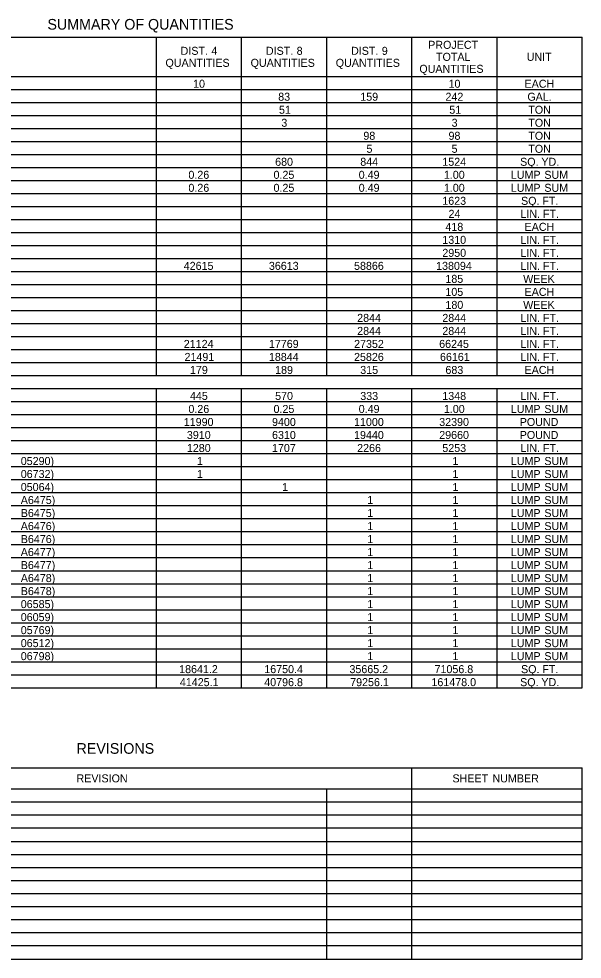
# Model space of a CAD drawing. Extents: x 544420 to 1930787, y -1947044 to 596640.
# Drawn here: x 552521 to 552943, y -1946914 to -1946209 of the extents above; entities that cross this region are included whole.
import ezdxf

# ---------------------------------------------------------------- set-up
doc = ezdxf.new("R2010")
doc.units = 0
doc.layers.add('Default', color=7, linetype='Continuous')

msp = doc.modelspace()

# ---------------------------------------------------------------- linework, layer by layer
at = {"layer": 'Default'}
for p, q in [((552192.61, -1946223.24), (552943.36, -1946223.24)), ((552624.05, -1946476.74), (552624.05, -1946223.24)), ((552624.05, -1946476.74), (552624.05, -1946223.24)), ((552687.91, -1946476.74), (552687.91, -1946223.24)), ((552687.91, -1946252.49), (552687.91, -1946223.24)), ((552751.77, -1946476.74), (552751.77, -1946223.24)), ((552751.77, -1946252.49), (552751.77, -1946223.24)), ((552815.63, -1946476.74), (552815.63, -1946223.24)), ((552879.5, -1946476.74), (552879.5, -1946223.24)), ((552879.5, -1946476.74), (552879.5, -1946223.24)), ((552943.36, -1946710.74), (552943.36, -1946223.24)), ((552192.61, -1946252.49), (552943.36, -1946252.49)), ((552192.61, -1946252.49), (552943.36, -1946252.49)), ((552192.61, -1946262.24), (552943.36, -1946262.24)), ((552192.61, -1946271.99), (552943.36, -1946271.99)), ((552192.61, -1946281.74), (552943.36, -1946281.74)), ((552192.61, -1946291.49), (552943.36, -1946291.49)), ((552192.61, -1946301.24), (552943.36, -1946301.24)), ((552192.61, -1946310.99), (552943.36, -1946310.99)), ((552192.61, -1946320.74), (552943.36, -1946320.74)), ((552192.61, -1946330.49), (552943.36, -1946330.49)), ((552192.61, -1946340.24), (552943.36, -1946340.24)), ((552192.61, -1946349.99), (552943.36, -1946349.99)), ((552192.61, -1946359.74), (552943.36, -1946359.74)), ((552192.61, -1946369.49), (552943.36, -1946369.49)), ((552192.61, -1946379.24), (552943.36, -1946379.24)), ((552192.61, -1946388.99), (552943.36, -1946388.99)), ((552192.61, -1946398.74), (552943.36, -1946398.74)), ((552192.61, -1946408.49), (552943.36, -1946408.49)), ((552192.61, -1946418.24), (552943.36, -1946418.24)), ((552192.61, -1946427.99), (552943.36, -1946427.99)), ((552192.61, -1946437.74), (552943.36, -1946437.74)), ((552192.61, -1946447.49), (552943.36, -1946447.49)), ((552192.61, -1946457.24), (552943.36, -1946457.24)), ((552192.61, -1946466.99), (552943.36, -1946466.99)), ((552192.61, -1946476.74), (552943.36, -1946476.74)), ((552192.61, -1946476.74), (552943.36, -1946476.74)), ((552192.61, -1946486.49), (552943.36, -1946486.49)), ((552192.61, -1946486.49), (552943.36, -1946486.49)), ((552624.05, -1946496.24), (552624.05, -1946486.49)), ((552624.05, -1946710.74), (552624.05, -1946486.49)), ((552687.91, -1946710.74), (552687.91, -1946486.49)), ((552751.77, -1946710.74), (552751.77, -1946486.49)), ((552815.63, -1946710.74), (552815.63, -1946486.49)), ((552879.5, -1946710.74), (552879.5, -1946486.49)), ((552879.5, -1946710.74), (552879.5, -1946486.49)), ((552192.61, -1946496.24), (552943.36, -1946496.24)), ((552192.61, -1946505.99), (552943.36, -1946505.99)), ((552624.05, -1946700.99), (552624.05, -1946505.99)), ((552192.61, -1946515.74), (552943.36, -1946515.74)), ((552563.11, -1946515.74), (552943.36, -1946515.74)), ((552192.61, -1946525.49), (552943.36, -1946525.49)), ((552563.11, -1946525.49), (552943.36, -1946525.49)), ((552192.61, -1946535.24), (552943.36, -1946535.24)), ((552563.11, -1946535.24), (552943.36, -1946535.24)), ((552192.61, -1946544.99), (552943.36, -1946544.99)), ((552263.3, -1946544.99), (552943.36, -1946544.99)), ((552192.61, -1946554.74), (552943.36, -1946554.74)), ((552263.3, -1946554.74), (552943.36, -1946554.74)), ((552192.61, -1946564.49), (552943.36, -1946564.49)), ((552263.3, -1946564.49), (552943.36, -1946564.49)), ((552192.61, -1946574.24), (552943.36, -1946574.24)), ((552263.3, -1946574.24), (552943.36, -1946574.24)), ((552192.61, -1946583.99), (552943.36, -1946583.99)), ((552263.3, -1946583.99), (552943.36, -1946583.99)), ((552192.61, -1946593.74), (552943.36, -1946593.74)), ((552263.3, -1946593.74), (552943.36, -1946593.74)), ((552192.61, -1946603.49), (552943.36, -1946603.49)), ((552263.3, -1946603.49), (552943.36, -1946603.49)), ((552192.61, -1946613.24), (552943.36, -1946613.24)), ((552263.3, -1946613.24), (552943.36, -1946613.24)), ((552192.61, -1946622.99), (552943.36, -1946622.99)), ((552263.3, -1946622.99), (552943.36, -1946622.99)), ((552192.61, -1946632.74), (552943.36, -1946632.74)), ((552263.3, -1946632.74), (552943.36, -1946632.74)), ((552192.61, -1946642.49), (552943.36, -1946642.49)), ((552263.3, -1946642.49), (552943.36, -1946642.49)), ((552192.61, -1946652.24), (552943.36, -1946652.24)), ((552263.3, -1946652.24), (552943.36, -1946652.24)), ((552192.61, -1946661.99), (552943.36, -1946661.99)), ((552263.3, -1946661.99), (552943.36, -1946661.99)), ((552192.61, -1946671.74), (552943.36, -1946671.74)), ((552263.3, -1946671.74), (552943.36, -1946671.74)), ((552192.61, -1946681.49), (552943.36, -1946681.49)), ((552263.3, -1946681.49), (552943.36, -1946681.49)), ((552192.61, -1946691.24), (552943.36, -1946691.24)), ((552263.3, -1946691.24), (552943.36, -1946691.24)), ((552192.61, -1946700.99), (552943.36, -1946700.99)), ((552563.11, -1946700.99), (552943.36, -1946700.99)), ((552192.61, -1946710.74), (552943.36, -1946710.74)), ((552192.61, -1946770.86), (552943.36, -1946770.86)), ((552815.63, -1946786.46), (552815.63, -1946770.86)), ((552815.63, -1946914.18), (552815.63, -1946770.86)), ((552943.36, -1946914.18), (552943.36, -1946770.86)), ((552192.61, -1946786.46), (552943.36, -1946786.46)), ((552751.77, -1946914.18), (552751.77, -1946786.46)), ((552751.77, -1946914.18), (552751.77, -1946786.46)), ((552192.61, -1946796.21), (552943.36, -1946796.21)), ((552192.61, -1946805.96), (552943.36, -1946805.96)), ((552192.61, -1946815.71), (552943.36, -1946815.71)), ((552192.61, -1946825.95), (552943.36, -1946825.95)), ((552192.61, -1946835.7), (552943.36, -1946835.7)), ((552192.61, -1946845.45), (552943.36, -1946845.45)), ((552192.61, -1946855.2), (552943.36, -1946855.2)), ((552192.61, -1946864.95), (552943.36, -1946864.95)), ((552192.61, -1946874.7), (552943.36, -1946874.7)), ((552192.61, -1946884.45), (552943.36, -1946884.45)), ((552192.61, -1946894.2), (552943.36, -1946894.2)), ((552192.61, -1946903.95), (552943.36, -1946903.95)), ((552192.61, -1946914.18), (552943.36, -1946914.18))]:
    msp.add_line(p, q, dxfattribs=at)

# ---------------------------------------------------------------- texts
for s, height, p in [('                                                                    SUMMARY OF QUANTITIES', 8, (552340.14, -1946217.49)), ('PROJECT', 6, (552827.85, -1946231.87)), ('DIST.', 6, (552642.15, -1946236.37)), (' 4', 6, (552663, -1946236.37)), ('DIST.', 6, (552706.11, -1946236.37)), (' 8', 6, (552726.96, -1946236.37)), ('DIST.', 6, (552769.98, -1946236.37)), (' 9', 6, (552790.83, -1946236.37)), ('TOTAL', 6, (552833.72, -1946240.87)), ('UNIT', 6, (552901.73, -1946240.87)), ('QUANTITIES', 6, (552630.8, -1946245.37)), ('QUANTITIES', 6, (552694.66, -1946245.37)), ('QUANTITIES', 6, (552758.52, -1946245.37)), ('QUANTITIES', 6, (552821.22, -1946249.87)), ('10', 6, (552651.52, -1946261.04)), ('10', 6, (552843.11, -1946261.04)), ('EACH', 6, (552900.12, -1946261.04)), ('83', 6, (552715.37, -1946270.79)), ('159', 6, (552776.9, -1946270.79)), ('242', 6, (552840.8, -1946270.79)), ('GAL.', 6, (552902.24, -1946270.79)), ('51', 6, (552715.95, -1946280.54)), ('51', 6, (552843.68, -1946280.54)), ('TON', 6, (552902.92, -1946280.54)), ('3', 6, (552717.7, -1946290.29)), ('3', 6, (552845.42, -1946290.29)), ('TON', 6, (552902.92, -1946290.29)), ('98', 6, (552779.23, -1946300.04)), ('98', 6, (552843.09, -1946300.04)), ('TON', 6, (552902.92, -1946300.04)), ('5', 6, (552781.54, -1946309.79)), ('5', 6, (552845.4, -1946309.79)), ('TON', 6, (552902.92, -1946309.79)), ('680', 6, (552713.05, -1946319.54)), ('844', 6, (552776.92, -1946319.54)), ('1524', 6, (552838.45, -1946319.54)), ('SQ.', 6, (552896.79, -1946319.54)), (' YD.', 6, (552910.5, -1946319.54)), ('0.26', 6, (552648.01, -1946329.29)), ('0.25', 6, (552711.85, -1946329.29)), ('0.49', 6, (552775.73, -1946329.29)), ('1.00', 6, (552839.61, -1946329.29)), ('LUMP', 6, (552889.8, -1946329.29)), (' SUM', 6, (552912.73, -1946329.29)), ('0.26', 6, (552648.01, -1946339.04)), ('0.25', 6, (552711.85, -1946339.04)), ('0.49', 6, (552775.73, -1946339.04)), ('1.00', 6, (552839.61, -1946339.04)), ('LUMP', 6, (552889.8, -1946339.04)), (' SUM', 6, (552912.73, -1946339.04)), ('1623', 6, (552838.43, -1946348.79)), ('SQ.', 6, (552897.49, -1946348.79)), (' FT.', 6, (552911.2, -1946348.79)), ('24', 6, (552843.11, -1946358.54)), ('LIN.', 6, (552897.02, -1946358.54)), (' FT.', 6, (552911.66, -1946358.54)), ('418', 6, (552840.76, -1946368.29)), ('EACH', 6, (552900.12, -1946368.29)), ('1310', 6, (552838.45, -1946378.04)), ('LIN.', 6, (552897.02, -1946378.04)), (' FT.', 6, (552911.66, -1946378.04)), ('2950', 6, (552838.45, -1946387.79)), ('LIN.', 6, (552897.02, -1946387.79)), (' FT.', 6, (552911.66, -1946387.79)), ('42615', 6, (552644.49, -1946397.54)), ('36613', 6, (552708.38, -1946397.54)), ('58866', 6, (552772.24, -1946397.54)), ('138094', 6, (552833.79, -1946397.54)), ('LIN.', 6, (552897.02, -1946397.54)), (' FT.', 6, (552911.66, -1946397.54)), ('185', 6, (552840.74, -1946407.29)), ('WEEK', 6, (552899.09, -1946407.29)), ('105', 6, (552840.74, -1946417.04)), ('EACH', 6, (552900.12, -1946417.04)), ('180', 6, (552840.78, -1946426.79)), ('WEEK', 6, (552899.09, -1946426.79)), ('2844', 6, (552774.59, -1946436.54)), ('2844', 6, (552838.45, -1946436.54)), ('LIN.', 6, (552897.02, -1946436.54)), (' FT.', 6, (552911.66, -1946436.54)), ('2844', 6, (552774.59, -1946446.29)), ('2844', 6, (552838.45, -1946446.29)), ('LIN.', 6, (552897.02, -1946446.29)), (' FT.', 6, (552911.66, -1946446.29)), ('21124', 6, (552644.53, -1946456.04)), ('17769', 6, (552708.37, -1946456.04)), ('27352', 6, (552772.27, -1946456.04)), ('66245', 6, (552836.08, -1946456.04)), ('LIN.', 6, (552897.02, -1946456.04)), (' FT.', 6, (552911.66, -1946456.04)), ('21491', 6, (552645.1, -1946465.79)), ('18844', 6, (552708.39, -1946465.79)), ('25826', 6, (552772.24, -1946465.79)), ('66161', 6, (552836.69, -1946465.79)), ('LIN.', 6, (552897.02, -1946465.79)), (' FT.', 6, (552911.66, -1946465.79)), ('179', 6, (552649.17, -1946475.54)), ('189', 6, (552713.03, -1946475.54)), ('315', 6, (552776.88, -1946475.54)), ('683', 6, (552840.76, -1946475.54)), ('EACH', 6, (552900.12, -1946475.54)), ('445', 6, (552649.15, -1946495.04)), ('570', 6, (552713.05, -1946495.04)), ('333', 6, (552776.9, -1946495.04)), ('1348', 6, (552838.43, -1946495.04)), ('LIN.', 6, (552897.02, -1946495.04)), (' FT.', 6, (552911.66, -1946495.04)), ('0.26', 6, (552648.01, -1946504.79)), ('0.25', 6, (552711.85, -1946504.79)), ('0.49', 6, (552775.73, -1946504.79)), ('1.00', 6, (552839.61, -1946504.79)), ('LUMP', 6, (552889.8, -1946504.79)), (' SUM', 6, (552912.73, -1946504.79)), ('11990', 6, (552644.53, -1946514.54)), ('9400', 6, (552710.72, -1946514.54)), ('11000', 6, (552772.25, -1946514.54)), ('32390', 6, (552836.12, -1946514.54)), ('POUND', 6, (552896.51, -1946514.54)), ('3910', 6, (552646.86, -1946524.29)), ('6310', 6, (552710.72, -1946524.29)), ('19440', 6, (552772.25, -1946524.29)), ('29660', 6, (552836.12, -1946524.29)), ('POUND', 6, (552896.51, -1946524.29)), ('1280', 6, (552646.86, -1946534.04)), ('1707', 6, (552710.71, -1946534.04)), ('2266', 6, (552774.57, -1946534.04)), ('5253', 6, (552838.43, -1946534.04)), ('LIN.', 6, (552897.02, -1946534.04)), (' FT.', 6, (552911.66, -1946534.04)), (' 05290)', 6, (552520.04, -1946543.79)), ('1', 6, (552654.42, -1946543.79)), ('1', 6, (552846.01, -1946543.79)), ('LUMP', 6, (552889.8, -1946543.79)), (' SUM', 6, (552912.73, -1946543.79)), (' 06732)', 6, (552520.04, -1946553.54)), ('1', 6, (552654.42, -1946553.54)), ('1', 6, (552846.01, -1946553.54)), ('LUMP', 6, (552889.8, -1946553.54)), (' SUM', 6, (552912.73, -1946553.54)), (' 05064)', 6, (552520.04, -1946563.29)), ('1', 6, (552718.28, -1946563.29)), ('1', 6, (552846.01, -1946563.29)), ('LUMP', 6, (552889.8, -1946563.29)), (' SUM', 6, (552912.73, -1946563.29)), (' A6475)', 6, (552520.04, -1946573.04)), ('1', 6, (552782.14, -1946573.04)), ('1', 6, (552846.01, -1946573.04)), ('LUMP', 6, (552889.8, -1946573.04)), (' SUM', 6, (552912.73, -1946573.04)), (' B6475)', 6, (552520.04, -1946582.79)), ('1', 6, (552782.14, -1946582.79)), ('1', 6, (552846.01, -1946582.79)), ('LUMP', 6, (552889.8, -1946582.79)), (' SUM', 6, (552912.73, -1946582.79)), (' A6476)', 6, (552520.04, -1946592.54)), ('1', 6, (552782.14, -1946592.54)), ('1', 6, (552846.01, -1946592.54)), ('LUMP', 6, (552889.8, -1946592.54)), (' SUM', 6, (552912.73, -1946592.54)), (' B6476)', 6, (552520.04, -1946602.29)), ('1', 6, (552782.14, -1946602.29)), ('1', 6, (552846.01, -1946602.29)), ('LUMP', 6, (552889.8, -1946602.29)), (' SUM', 6, (552912.73, -1946602.29)), (' A6477)', 6, (552520.04, -1946612.04)), ('1', 6, (552782.14, -1946612.04)), ('1', 6, (552846.01, -1946612.04)), ('LUMP', 6, (552889.8, -1946612.04)), (' SUM', 6, (552912.73, -1946612.04)), (' B6477)', 6, (552520.04, -1946621.79)), ('1', 6, (552782.14, -1946621.79)), ('1', 6, (552846.01, -1946621.79)), ('LUMP', 6, (552889.8, -1946621.79)), (' SUM', 6, (552912.73, -1946621.79)), (' A6478)', 6, (552520.04, -1946631.54)), ('1', 6, (552782.14, -1946631.54)), ('1', 6, (552846.01, -1946631.54)), ('LUMP', 6, (552889.8, -1946631.54)), (' SUM', 6, (552912.73, -1946631.54)), (' B6478)', 6, (552520.04, -1946641.29)), ('1', 6, (552782.14, -1946641.29)), ('1', 6, (552846.01, -1946641.29)), ('LUMP', 6, (552889.8, -1946641.29)), (' SUM', 6, (552912.73, -1946641.29)), (' 06585)', 6, (552520.04, -1946651.04)), ('1', 6, (552782.14, -1946651.04)), ('1', 6, (552846.01, -1946651.04)), ('LUMP', 6, (552889.8, -1946651.04)), (' SUM', 6, (552912.73, -1946651.04)), (' 06059)', 6, (552520.04, -1946660.79)), ('1', 6, (552782.14, -1946660.79)), ('1', 6, (552846.01, -1946660.79)), ('LUMP', 6, (552889.8, -1946660.79)), (' SUM', 6, (552912.73, -1946660.79)), (' 05769)', 6, (552520.04, -1946670.54)), ('1', 6, (552782.14, -1946670.54)), ('1', 6, (552846.01, -1946670.54)), ('LUMP', 6, (552889.8, -1946670.54)), (' SUM', 6, (552912.73, -1946670.54)), (' 06512)', 6, (552520.04, -1946680.29)), ('1', 6, (552782.14, -1946680.29)), ('1', 6, (552846.01, -1946680.29)), ('LUMP', 6, (552889.8, -1946680.29)), (' SUM', 6, (552912.73, -1946680.29)), (' 06798)', 6, (552520.04, -1946690.04)), ('1', 6, (552782.14, -1946690.04)), ('1', 6, (552846.01, -1946690.04)), ('LUMP', 6, (552889.8, -1946690.04)), (' SUM', 6, (552912.73, -1946690.04)), ('18641.2', 6, (552641.05, -1946699.79)), ('16750.4', 6, (552704.9, -1946699.79)), ('35665.2', 6, (552768.78, -1946699.79)), ('71056.8', 6, (552832.61, -1946699.79)), ('SQ.', 6, (552897.49, -1946699.79)), (' FT.', 6, (552911.2, -1946699.79)), ('41425.1', 6, (552641.6, -1946709.54)), ('40796.8', 6, (552704.88, -1946709.54)), ('79256.1', 6, (552769.33, -1946709.54)), ('161478.0', 6, (552830.29, -1946709.54)), ('SQ.', 6, (552896.79, -1946709.54)), (' YD.', 6, (552910.5, -1946709.54)), ('REVISIONS', 8, (552564.08, -1946760.23)), ('REVISION', 6, (552564.08, -1946781.66)), ('SHEET', 6, (552846.06, -1946781.66)), (' NUMBER', 6, (552873.85, -1946781.66))]:
    msp.add_text(s, height=height, dxfattribs=at).set_placement(p)

doc.saveas('drawing.dxf')
